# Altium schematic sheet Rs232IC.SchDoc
size A4; CheckedBy: Everyone; DocumentNumber: 3; SheetNumber: 3; SheetTotal: 4
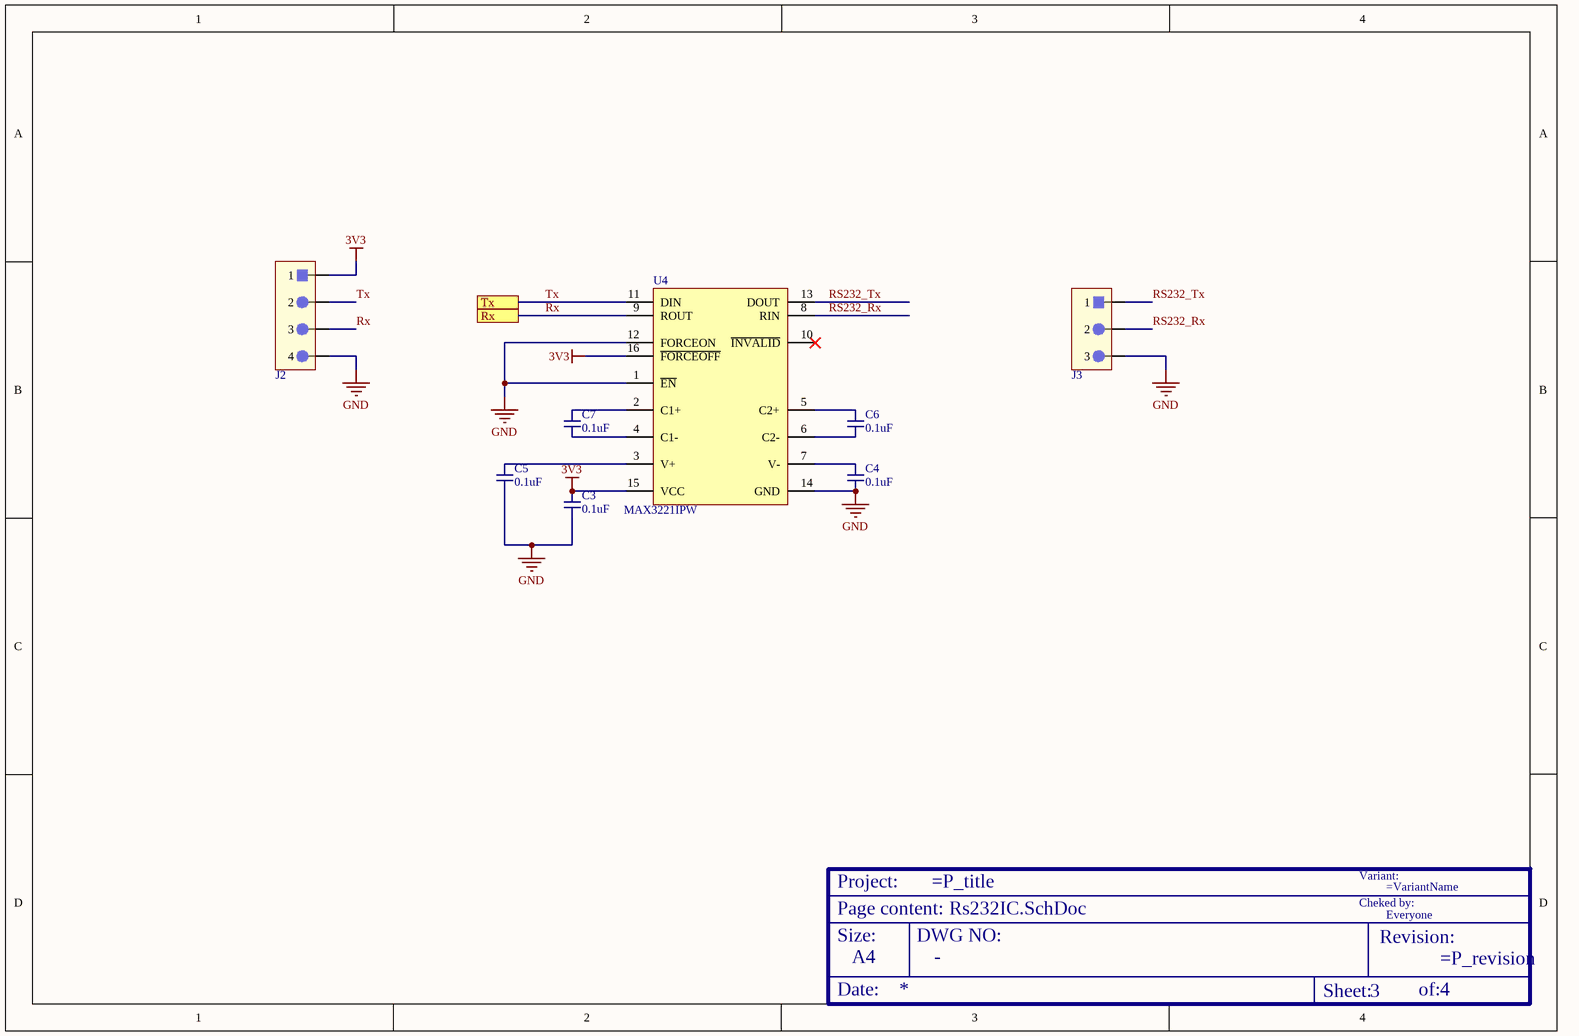
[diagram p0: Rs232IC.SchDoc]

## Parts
?  Size: A4  (hidden comment: TitleBox)  (graphical)
C3  value 0.1uF  [0603C]  (hidden comment: Ceramic Capacitor)
C4  value 0.1uF  [0603C]  (hidden comment: Ceramic Capacitor)
C5  value 0.1uF  [0603C]  (hidden comment: Ceramic Capacitor)
C6  value 0.1uF  [0603C]  (hidden comment: Ceramic Capacitor)
C7  value 0.1uF  [0603C]  (hidden comment: Ceramic Capacitor)
J2  Conector  [61300411121]  (value not drawn)
J3  Conector  [61300311121]  (value not drawn)
U4  value MAX3221IPW  [TI-PW16_M]  (hidden comment: RS232 Serie CI)

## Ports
Rx, Tx

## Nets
3V3: C3.1 J2.1 U4.15(VCC) U4.16(~{FORCEOFF})
GND: C3.2 C4.2 C5.2 J2.4 J3.3 U4.1(~{EN}) U4.12(FORCEON) U4.14(GND)
RS232_Rx: J3.2 U4.8(RIN)
RS232_Tx: J3.1 U4.13(DOUT)
Rx: J2.3 U4.9(ROUT) ; port Rx
Tx: J2.2 U4.11(DIN) ; port Tx
NetC4_1: C4.1 U4.7(V-)
NetC5_1: C5.1 U4.3(V+)
NetC6_1: C6.1 U4.5(C2+)
NetC6_2: C6.2 U4.6(C2-)
NetC7_1: C7.1 U4.2(C1+)
NetC7_2: C7.2 U4.4(C1-)

Not connected (* = marked no-connect by the designer): U4 10(~{INVALID})*

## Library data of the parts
? = TitleBox_1: coordenadas: (610;20) Size A4
C3-C7 = CC
J2 = Conector 4 pins: Value: 4
J3 = Conector 3 pins: Value: 3
U4 = MAX3221IPW: 3-V to 5.5-V Single-Channel RS-232 Line Driver / Receiver with ±15-kV ESD Protection, -40 to 85 degC, 16-Pin TSSOP (PW), Green (RoHS & no Sb/Br); Drivers Per Package: 1; Single Supply: TRUE; ESD HBM(kV): +/-15; Supply Voltage(s)(V): 3.3 or 5.0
